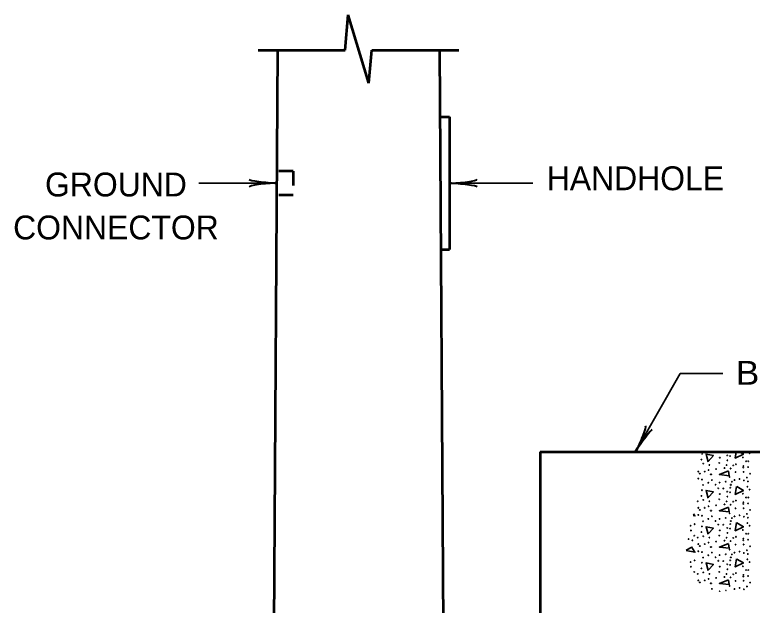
# Model space of a CAD drawing. Extents: x -1 to 679, y 0 to 440.
# Drawn here: x 261.3 to 338.6, y 173.8 to 235.6 of the extents above; entities that cross this region are included whole.
import ezdxf
from ezdxf.enums import TextEntityAlignment as Align

# ---------------------------------------------------------------- set-up
doc = ezdxf.new("R2010")
doc.units = 0
doc.linetypes.add('SHORT_DASHED', pattern=[2.7, 1.5, -1.2])
doc.layers.add('1', color=7, linetype='Continuous', lineweight=35)

msp = doc.modelspace()

# ---------------------------------------------------------------- linework, layer by layer
at = {"layer": '1', "lineweight": 53}
for p, q in [((295.949, 231.916), (296.272, 235.608)), ((298.434, 228.44), (296.272, 235.608)), ((286.843, 231.916), (295.949, 231.916)), ((288.843, 231.916), (288.34, 146.328)), ((298.434, 228.44), (298.738, 231.916)), ((298.738, 231.916), (307.843, 231.916)), ((305.843, 231.916), (306.347, 146.303)), ((305.885, 224.914), (306.885, 224.914)), ((306.885, 224.914), (306.885, 211.035)), ((305.966, 211.035), (306.885, 211.035)), ((316.37, 189.85), (316.37, 120.49)), ((316.37, 189.85), (333.37, 189.85))]:
    msp.add_line(p, q, dxfattribs=at)
at = {"layer": '1', "linetype": 'SHORT_DASHED', "lineweight": 53}
for p, q in [((290.511, 219.225), (288.761, 219.225)), ((290.511, 219.225), (290.511, 216.725)), ((290.511, 216.725), (288.761, 216.725))]:
    msp.add_line(p, q, dxfattribs=at)
at = {"layer": '1'}
for p, q in [((288.761, 217.975), (280.606, 217.975)), ((306.885, 217.975), (315.62, 217.975)), ((332.269, 179.869), (331.673, 179.544))]:
    msp.add_line(p, q, dxfattribs=at)
for points in [[(326.352, 189.85), (331.051, 198.036), (335.516, 198.036)], [(333.989, 188.809), (333.749, 189.609), (334.529, 189.449), (333.969, 188.849)], [(337.247, 189.85), (337.669, 189.609), (336.809, 189.189), (336.904, 189.85)], [(336.089, 187.849), (335.149, 187.469), (336.189, 187.349), (336.089, 187.809)], [(336.969, 186.209), (337.669, 185.809), (336.809, 185.389), (336.929, 186.229)], [(333.989, 185.009), (333.749, 185.809), (334.529, 185.649), (333.969, 185.049)], [(336.089, 184.049), (335.149, 183.669), (336.189, 183.549), (336.089, 184.009)], [(332.39, 183.166), (332.589, 183.129), (332.439, 183.362)], [(336.969, 182.409), (337.669, 182.009), (336.809, 181.589), (336.929, 182.429)], [(333.989, 181.209), (333.749, 182.009), (334.529, 181.849), (333.969, 181.249)], [(336.089, 180.249), (335.149, 179.869), (336.189, 179.749), (336.089, 180.209)], [(331.672, 179.498), (332.589, 179.329), (332.229, 179.889)], [(336.969, 178.609), (337.669, 178.209), (336.809, 177.789), (336.929, 178.629)], [(333.989, 177.409), (333.749, 178.209), (334.529, 178.049), (333.969, 177.449)], [(336.089, 176.449), (335.149, 176.069), (336.189, 175.949), (336.089, 176.409)]]:
    msp.add_lwpolyline(points, dxfattribs=at)
at = {"layer": '1', "lineweight": 53}
msp.add_lwpolyline([(333.37, 189.85), (342.37, 189.85), (343.87, 188.35), (346.208, 176.58)], dxfattribs=at)
at = {"layer": '1'}
for centre in [(335.555, 189.805), (335.979, 189.473), (336.27, 189.407), (338.311, 189.699), (333.275, 189.036), (333.461, 188.612), (335.13, 188.678), (335.197, 189.222), (335.992, 188.956), (336.88, 188.545), (337.622, 189.261), (337.953, 188.864), (338.179, 188.864), (332.944, 187.781), (333.62, 187.781), (334.017, 187.94), (334.11, 188.466), (334.799, 188.046), (335.687, 188.139), (335.899, 188.453), (336.323, 188.099), (336.602, 188.426), (336.853, 187.728), (337.649, 188.192), (337.662, 188.36), (337.688, 187.742), (338.152, 188.245), (332.944, 187.039), (333.103, 187.569), (333.328, 186.946), (334.243, 187.476), (334.296, 187.476), (336.217, 187.211), (337.264, 186.999), (338.033, 187.145), (338.364, 187.556), (333.447, 186.376), (333.991, 186.615), (334.362, 186.893), (334.759, 186.403), (335.17, 186.628), (335.82, 186.721), (336.35, 186.389), (336.456, 186.707), (336.734, 186.88), (337.715, 186.853), (338.086, 186.19), (338.139, 186.747), (333.315, 185.832), (335.038, 186.031), (335.197, 185.422), (335.555, 186.005), (335.979, 185.673), (336.27, 185.607), (336.283, 186.084), (337.622, 185.461), (338.311, 185.899), (332.877, 184.666), (333.275, 185.236), (333.461, 184.812), (334.11, 184.666), (335.13, 184.878), (335.899, 184.653), (335.992, 185.156), (336.88, 184.745), (337.953, 185.064), (338.179, 185.064), (332.944, 183.981), (333.62, 183.981), (334.017, 184.14), (334.799, 184.246), (335.687, 184.339), (336.323, 184.299), (336.602, 184.626), (336.853, 183.928), (337.649, 184.392), (337.662, 184.56), (337.688, 183.942), (338.152, 184.445), (332.944, 183.239), (333.103, 183.769), (333.328, 183.146), (334.243, 183.676), (334.296, 183.676), (334.362, 183.093), (336.217, 183.411), (337.264, 183.199), (338.033, 183.345), (338.364, 183.756), (333.447, 182.576), (333.991, 182.815), (334.759, 182.603), (335.17, 182.828), (335.82, 182.921), (336.35, 182.589), (336.456, 182.907), (336.734, 183.08), (337.715, 183.053), (338.086, 182.39), (338.139, 182.947), (332.135, 182.099), (332.175, 181.608), (332.546, 182.271), (333.315, 182.032), (335.038, 182.231), (335.197, 181.622), (335.555, 182.205), (335.979, 181.873), (336.27, 181.807), (336.283, 182.284), (337.622, 181.661), (338.311, 182.099), (332.52, 181.065), (332.877, 180.866), (333.275, 181.436), (333.461, 181.012), (334.11, 180.866), (335.13, 181.078), (335.899, 180.853), (335.992, 181.356), (336.602, 180.826), (336.88, 180.945), (337.953, 181.264), (338.179, 181.264), (331.923, 180.707), (332.321, 180.579), (332.944, 180.181), (333.62, 180.181), (334.017, 180.34), (334.799, 180.446), (335.687, 180.539), (336.323, 180.499), (336.853, 180.128), (337.649, 180.592), (337.662, 180.76), (337.688, 180.142), (338.152, 180.645), (332.944, 179.439), (333.103, 179.969), (333.328, 179.346), (334.243, 179.876), (334.296, 179.876), (334.362, 179.293), (336.217, 179.611), (336.734, 179.28), (337.264, 179.399), (337.715, 179.253), (338.033, 179.545), (338.364, 179.956), (332.546, 178.471), (333.447, 178.776), (333.991, 179.015), (334.759, 178.803), (335.17, 179.028), (335.82, 179.121), (336.283, 178.484), (336.35, 178.789), (336.456, 179.107), (338.086, 178.59), (338.139, 179.147), (332.135, 178.299), (332.175, 177.808), (333.315, 178.232), (335.038, 178.431), (335.197, 177.822), (335.555, 178.405), (335.979, 178.073), (336.27, 178.007), (337.622, 177.861), (338.311, 178.299), (332.52, 177.265), (332.877, 177.066), (333.275, 177.636), (333.461, 177.212), (334.11, 177.066), (335.13, 177.278), (335.899, 177.053), (335.992, 177.556), (336.602, 177.026), (336.88, 177.145), (337.662, 176.96), (337.953, 177.464), (338.179, 177.464), (332.944, 176.381), (333.103, 176.169), (333.62, 176.381), (334.017, 176.54), (334.799, 176.646), (335.687, 176.739), (336.323, 176.699), (336.853, 176.328), (337.649, 176.792), (337.688, 176.342), (338.152, 176.845), (338.364, 176.156), (334.243, 176.076), (334.296, 176.076), (334.362, 175.493), (336.217, 175.811), (336.734, 175.48), (337.264, 175.599), (337.715, 175.453), (338.033, 175.745)]:
    msp.add_circle(centre, 0.0265, dxfattribs=at)
for centre, start, end in [((333.315, 189.632), 253.75586, 77.13253), ((335.038, 189.831), 134.48926, 45.51074), ((335.17, 175.228), 14.9342, 178.72641), ((335.82, 175.321), 8.19211, 187.61765)]:
    msp.add_arc(centre, 0.0265, start, end, dxfattribs=at)
at = {"layer": '1', "lineweight": 40}
for centre, major_axis, ratio, start_param, end_param in [((287.67, 217.698), (1.786, 0.156), 0.122415, 0.896353, 3.141593), ((287.67, 217.698), (1.786, 0.156), 0.122415, 0.896353, 3.141593), ((287.641, 218.186), (1.756, -0.176), 0.07063, 3.140715, 5.41811), ((287.641, 218.186), (1.756, -0.176), 0.07063, 3.140715, 5.41811), ((308.005, 217.763), (-1.756, 0.176), 0.07063, 3.140715, 5.41811), ((307.976, 218.251), (-1.786, -0.156), 0.122415, 0.896353, 3.141593), ((326.656, 190.934), (-0.754, -1.626), 0.122415, 0.896353, 3.141593), ((326.656, 190.934), (-0.754, -1.626), 0.122415, 0.896353, 3.141593), ((327.093, 190.717), (1.027, 1.436), 0.07063, 6.282307, 8.559703), ((327.093, 190.717), (1.027, 1.436), 0.07063, 6.282307, 8.559703)]:
    msp.add_ellipse(centre, major_axis=major_axis, ratio=ratio, start_param=start_param, end_param=end_param, dxfattribs=at)

# ---------------------------------------------------------------- texts
at = {"layer": '1'}
msp.add_text('HANDHOLE', height=2.5, dxfattribs=at).set_placement((317.065, 217.237))
for s, p in [('GROUND', (271.934, 216.586)), ('CONNECTOR', (271.934, 212.086))]:
    msp.add_text(s, height=2.5, dxfattribs=at).set_placement(p, align=Align.CENTER)
at = {"layer": '1', "width": 1.1}
msp.add_text('BRIDGE PARAPET', height=2.5, dxfattribs=at).set_placement((336.878, 196.867))

doc.saveas('drawing.dxf')
